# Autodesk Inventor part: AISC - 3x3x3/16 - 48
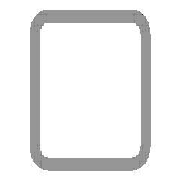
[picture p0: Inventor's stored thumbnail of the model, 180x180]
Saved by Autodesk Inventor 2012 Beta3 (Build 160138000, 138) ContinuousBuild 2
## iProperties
_CCFamilyMember: 9
_CCFamilyDisplayName: ANSI AISC (Square) - Tube
_FrameMemberDoc: Frame Member File
_Version: 15.0.0
_GetPNFromCC: 1
Created: 2011-01
Part Number: AISC - 3x3x3/16 - 48
Material: Steel, Mild
Description: Tube
Document SubType Name: Modeling
Standard: ANSI
Designer: Beta-8540w
Standards Organization: ANSI
Language: en-US
Size Designation: 3x3x3/16
Categories: <MemberInstance><Categories><Category DisplayName="Structural Shapes" InternalName="089c4875-fa83-4c05-b084-43b9cc11f5ed" Mnemonic="GRDR"><CategoryParameter Dis
Stock Number: 3x3x3/16
Density: 7.86 g/cm^3
IsCustomPart: 1
G_L: 48.000 in
G_W: 3.000 in
G_H: 3.000 in
Author: Beta-8540w
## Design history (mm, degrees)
node "Start plane"
node "End plane"
sketch "Sketch"
  geometry: L1 (-38.1, -28.575)-(-38.1, 28.575); L2 (-28.575, 38.1)-(28.575, 38.1); L3 (38.1, 28.575)-(38.1, -28.575); L4 (28.575, -38.1)-(-28.575, -38.1); L5 (-28.575, 33.337)-(28.575, 33.338); L6 (33.338, 28.575)-(33.338, -28.575); L7 (28.575, -33.337)-(-28.575, -33.338); L8 (-33.338, -28.575)-(-33.338, 28.575); L9 (0, 56.102)-(0, -56.102) reference; L10 (-56.102, 0)-(56.102, 0) reference; A1 r 9.525 centre (-28.575, -28.575) between (-38.1, -28.575) and (-28.575, -38.1); A2 r 9.525 centre (-28.575, 28.575) between (-28.575, 38.1) and (-38.1, 28.575); A3 r 9.525 centre (28.575, 28.575) between (38.1, 28.575) and (28.575, 38.1); A4 r 9.525 centre (28.575, -28.575) between (28.575, -38.1) and (38.1, -28.575); A5 r 4.763 centre (-28.575, 28.575) between (-28.575, 33.337) and (-33.338, 28.575); A6 r 4.763 centre (28.575, 28.575) between (33.338, 28.575) and (28.575, 33.338); A7 r 4.763 centre (28.575, -28.575) between (28.575, -33.337) and (33.338, -28.575); A8 r 4.763 centre (-28.575, -28.575) between (-33.338, -28.575) and (-28.575, -33.338)
  constraints: 16 end point, 16 point on circle, 8 centre point, 8 tangent, 4 parallel, 3 equal radius, 2 perpendicular, 7 other
  dimensions: "d10" = 76.2 distance between parallel lines of L2 L4 (= G_H); "d11" = 76.2 distance between parallel lines of L1 L3 (= G_W); "d12" = 4.7625 distance between parallel lines of L3 L6 (= G_T); "d15" = 38.1 distance between parallel lines of L2 L10 (= 0.5 x d10); "d16" = 38.1 distance between parallel lines of L9 L3 (= 0.5 x d11); "d17" = 9.525 radius of A1 (= G_IR)
extrude "Body" new body sketch "Sketch" stored distance "d3" = 1219.2 (= G_L); taper "d4" = 0 deg
node "Driven Length"
  sketch "Sketch3"
    geometry: L1 (0, 0)-(10, 0) reference
    constraints: 2 end point, 1 horizontal
  workplane "Work Plane3"
  sketch "Sketch4"
    geometry: L1 (-2, 0)-(12, 0) reference; L2 (-2, 1219.2)-(12, 1219.2) reference
    dimensions: "d19" = 1219.2 distance between parallel lines of L1 L2 (derived)
body "Solid1"
other parameters: "G_W" = 76.2 [user parameter; used in 1 equation term], "G_H" = 76.2 [user parameter; used in 1 equation term], "G_T" = 4.7625 [user parameter; used in 1 equation term], "G_IR" = 9.525 [user parameter; used in 1 equation term], "G_L" = 1219.2 (= d19) [user parameter; used in 1 equation term], "G_OFFSET_START" = 0 [user parameter; used in 1 equation term], "G_OFFSET_END" = 0 [user parameter; used in 1 equation term], "d13" = 0 (computed from G_OFFSET_START), "d14" = 1219.2 (= G_OFFSET_END + B_L), "B_L" = 1219.2 [user parameter; used in 1 equation term], "d18" = 90 deg
